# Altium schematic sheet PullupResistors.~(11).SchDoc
size A4
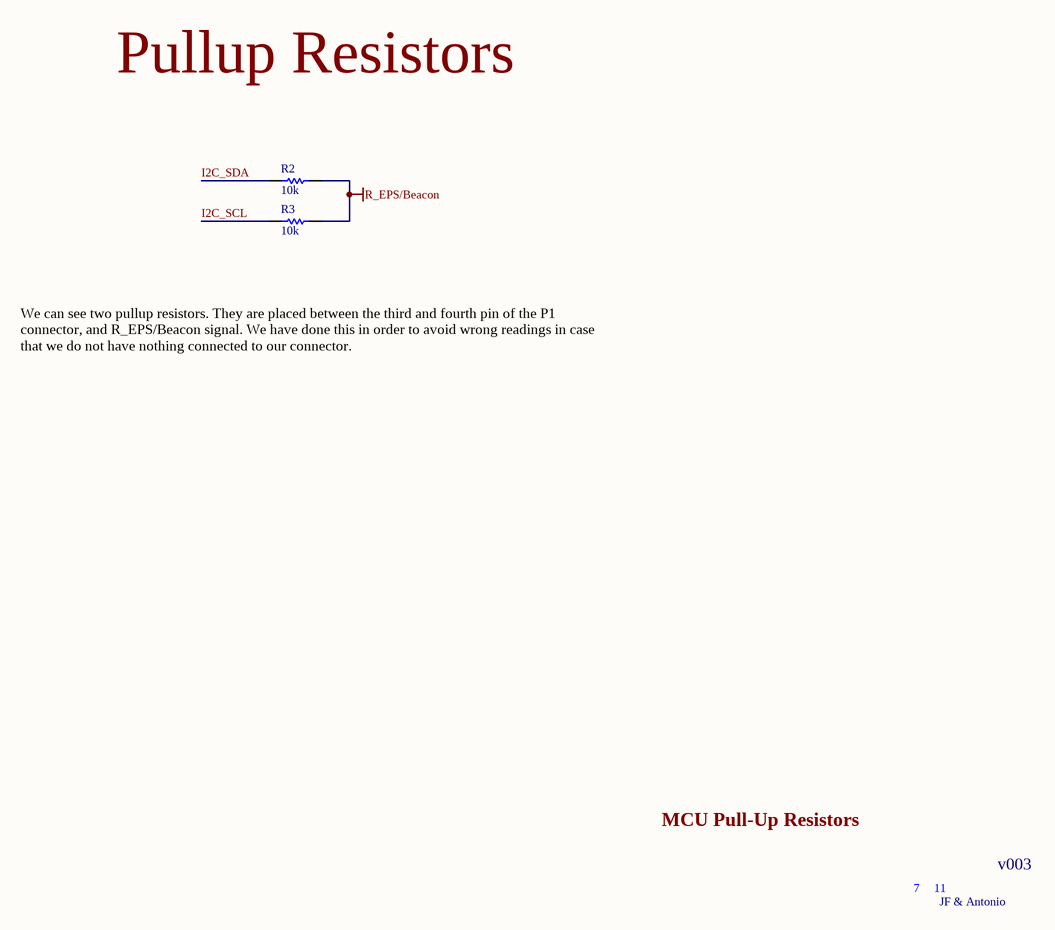
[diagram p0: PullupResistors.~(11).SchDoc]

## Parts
R2  10k  [R10k]
R3  10k  [R10k]

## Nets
R_EPS/Beacon: R2.2 R3.2
I2C_SCL: R3.1
I2C_SDA: R2.1

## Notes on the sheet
- Pullup Resistors
- We can see two pullup resistors. They are placed between the third and fourth pin of the P1 connector, and R_EPS/Beacon signal. We have done this in order to avoid wrong readings in case that we do not have nothing connected to our connector.
- MCU Pull-Up Resistors
- 7
- 11
- v003
- JF & Antonio

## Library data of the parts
R2 R3 = Res1: Resistor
